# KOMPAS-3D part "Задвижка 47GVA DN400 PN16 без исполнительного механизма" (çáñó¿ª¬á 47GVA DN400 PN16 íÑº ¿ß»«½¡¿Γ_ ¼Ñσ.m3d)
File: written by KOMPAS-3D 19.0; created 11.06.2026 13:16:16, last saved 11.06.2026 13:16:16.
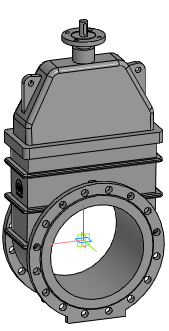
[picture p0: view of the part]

Document properties: Автор: Евгений; Полное имя файла: Z:\3.Личные\kachalov\001_3d для проектировщиков\2.2 Тип 47GVA, 47GVA.Z\_stp\_stp_Задвижка 47GVA DN40-DN1000 без исп.мех\Задвижка 47GVA DN400 PN16 без исполнит_ мех.m3d

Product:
- Part/product: Задвижка 47GVA DN400 PN16 без исполнительного механизма

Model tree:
1. Операция без истории:1  (labels: Задвижка 47GVA DN400 PN16 без исполнительного механизма)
